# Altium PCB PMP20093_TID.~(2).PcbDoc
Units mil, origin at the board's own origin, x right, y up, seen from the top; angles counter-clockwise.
Board outline 4950 x 3450 mil, 2 copper layers (Top Layer, Bottom Layer), stack 62 mil thick; 35 components, 27 nets, 63 pads, 0 vias.
Unrouted connection lines stored in the file: 39.
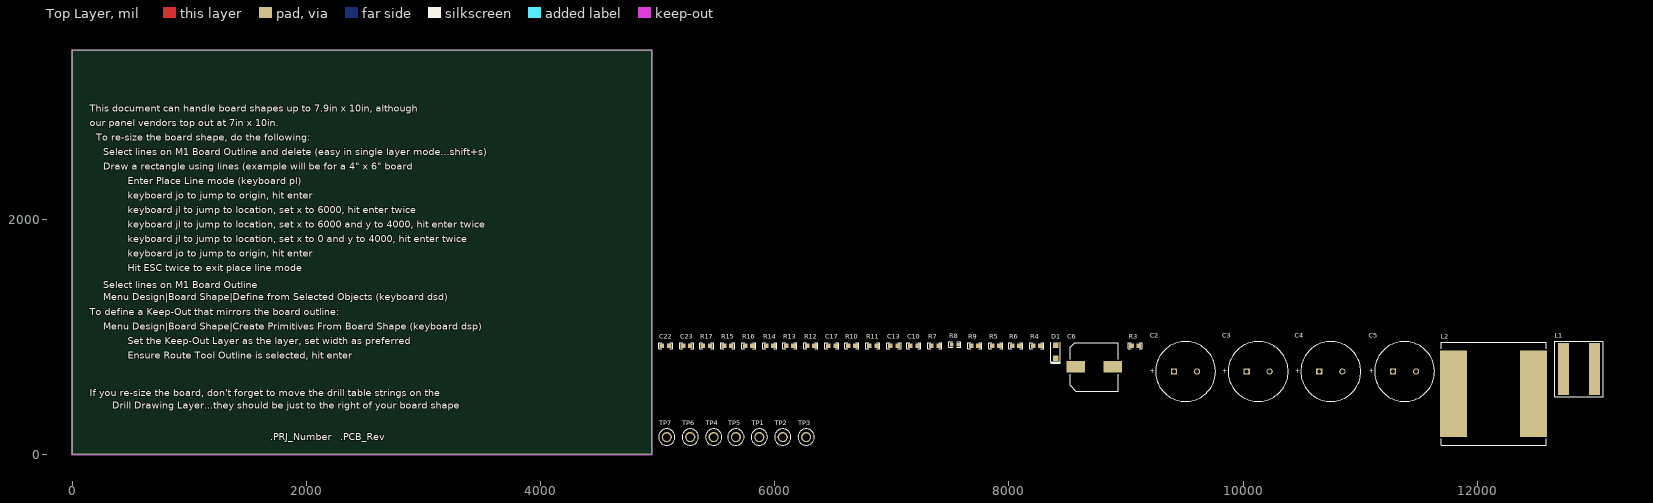
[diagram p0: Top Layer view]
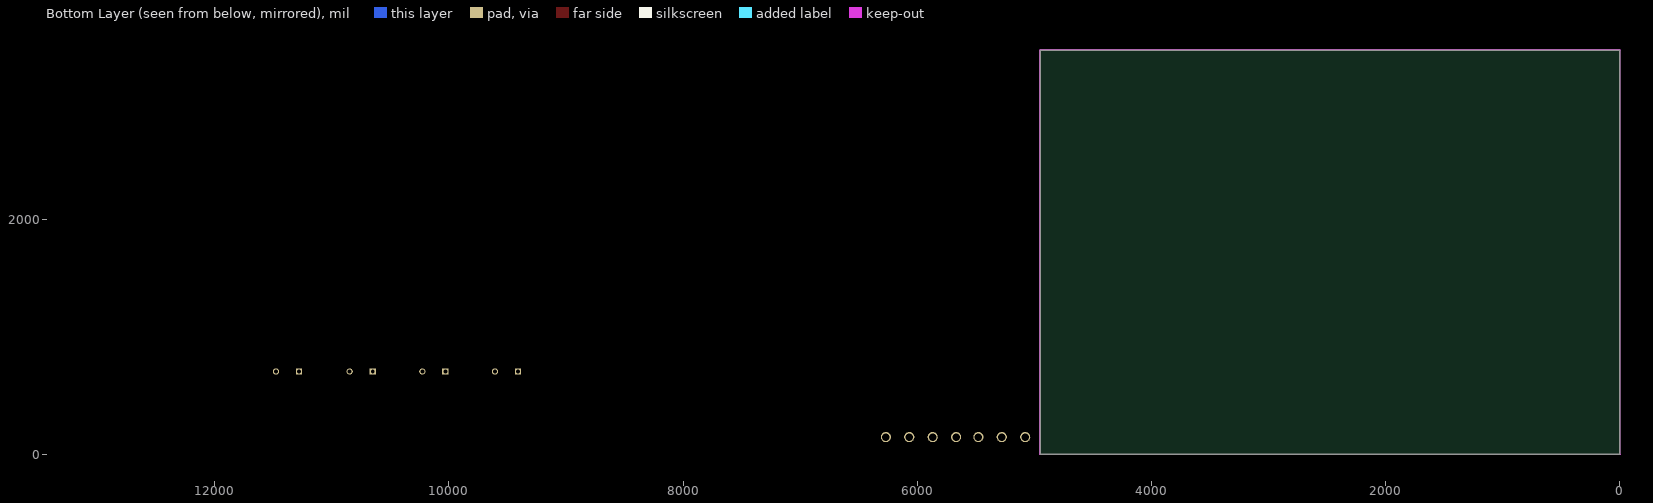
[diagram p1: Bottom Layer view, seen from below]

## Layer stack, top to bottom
Top Solder: solder mask 0.4, Solder Resist, Dk 3.5
Top Layer: signal copper 1.4
Dielectric1: core 59.2, FR-4, Dk 4.8
Bottom Layer: signal copper 1.4
Bottom Solder: solder mask 0.4, Solder Resist, Dk 3.5

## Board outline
0,0 4950,0 4950,3450 0,3450

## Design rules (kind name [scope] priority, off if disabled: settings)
AcuteAngle [All] p1: minimum=4.50000000000000E+0001 checktracksonly=FALSE
AssemblyTestPointUsage [All] p1: valid=2
Clearance Clearance_Keepouts [((IsTrack Or IsArc) And Not InPoly) And IsFree and IsKeepOut vs ((IsTrack Or IsArc) And Not InPoly) And IsFree and IsKeepOut] p1: gap=0
Clearance Clearance_BoardEdge_MountingHoles [OnCopper and InComponentClass('Mounting Holes') vs IsKeepOut] p2: gap=40
Clearance Clearance_BoardEdge_Poly [OnCopper and InPoly vs IsKeepOut] p3: gap=25
Clearance Clearance_BoardEdge [OnCopper and Not InComponentClass('Logo') and not InComponentClass('FiducialMark') and not InRegion(1000,500,4000,800) and Not IsKeepout vs IsKeepOut] p4: gap=75
Clearance Clearance_Poly [InPolygon] p5: gap=25
Clearance [All] p6: gap=7.87
ComponentClearance ComponentClearance_MountingHoles_FiducialMarks [InComponentClass('Mounting Holes') vs InComponentClass('FiducialMark')] p1: gap=50 collisioncheckmode=3 verticalgap=10 showdistances=FALSE
ComponentClearance ComponentClearance_Shunt [InComponentClass('Header') vs InComponentClass('Shunt')] p2: gap=0 collisioncheckmode=3 verticalgap=0 showdistances=FALSE
ComponentClearance ComponentClearance_Logo [InComponentClass('Logo')] p3: gap=50 collisioncheckmode=3 verticalgap=10 showdistances=FALSE
ComponentClearance ComponentClearance_ScrewToNut [(HasFootprint('NY PMS 440 0025 PH')) vs (HasFootprint('Keystone_1902C'))] p4: gap=5 collisioncheckmode=3 verticalgap=10 showdistances=FALSE
ComponentClearance ComponentClearance_MountingHoles [InComponentClass('Mounting Holes')] p5: gap=250 collisioncheckmode=3 verticalgap=100000 showdistances=FALSE
ComponentClearance ComponentClearance_SmallPassives [HasFootprint('0201*') or HasFootprint('0402*') or HasFootprint('0508') or HasFootprint('0603*') or HasFootprint('0612') or HasFootprint('0805*') or HasFootprint('0815*') or HasFootprint('0830*') or HasFootprint('1206*') or HasFootprint('1210*') or HasFootprint('1808*') or HasFootprint('1812*') or HasFootprint('1825*') or HasFootprint('2010*') or HasFootprint('2220*') or HasFootprint('2225*') or HasFootprint('2512*') or HasFootprint('2728*') or HasFootprint('3518*') vs HasFootprint('0201*') or HasFootprint('0402*') or HasFootprint('0508') or HasFootprint('0603*') or HasFootprint('0612') or HasFootprint('0805*') or HasFootprint('0815*') or HasFootprint('0830*') or HasFootprint('1206*') or HasFootprint('1210*') or HasFootprint('1808*') or HasFootprint('1812*') or HasFootprint('1825*') or HasFootprint('2010*') or HasFootprint('2220*') or HasFootprint('2225*') or HasFootprint('2512*') or HasFootprint('2728*') or HasFootprint('3518*')] p6: gap=20 collisioncheckmode=3 verticalgap=10 showdistances=FALSE
ComponentClearance ComponentClearance_THtoSMT [IsThruComponent vs IsSMTComponent] p7: gap=100 collisioncheckmode=3 verticalgap=30 showdistances=FALSE
ComponentClearance ComponentClearance_THtoTH [IsThruComponent vs IsThruComponent] p8: gap=118.11 collisioncheckmode=3 verticalgap=30 showdistances=FALSE
ComponentClearance [All] p9: gap=40 collisioncheckmode=3 verticalgap=10 showdistances=FALSE
DiffPairsRouting [All] p1: maxlimit=100 minlimit=10 mostfreqgap=10 toplayer_minwidth=15 toplayer_maxwidth=15 toplayer_prefwidth=15 bottomlayer_minwidth=15 bottomlayer_maxwidth=15 bottomlayer_prefwidth=15 maxuncoupledlength=1000
FabricationTestPointUsage TestPointUsage [All] p1: valid=2 allowmultiple=FALSE
FabricationTestpoint Testpoint [All] p1: side=3 testpointundercomponent=TRUE minsize=40 maxsize=100 preferedsize=60 minholesize=0 maxholesize=40 preferedholesize=32 testpointgrid=1 allowsidetop=TRUE allowsidebottom=TRUE usegrid=TRUE gridtolerance=0.01
FanoutControl Fanout_LCC [IsLCC] p1: bgadir=Out bgaviamode=Centered fanoutstyle=Auto fanoutdirection=Alternating viagrid=1 // Fanout_LCC (Default Rule)
FanoutControl Fanout_BGA [IsBGA] p2: bgadir=Out bgaviamode=Centered fanoutstyle=Auto fanoutdirection=Alternating viagrid=1 // Fanout_BGA (Default Rule)
FanoutControl Fanout_Default [All] p4: bgadir=Out bgaviamode=Centered fanoutstyle=Auto fanoutdirection=Alternating viagrid=1 // Fanout_Default (Default Rule)
FanoutControl Fanout_Small [(CompPinCount < 5)] p5: bgadir=Out bgaviamode=Centered fanoutstyle=Auto fanoutdirection=OutThenIn viagrid=1 // Fanout_Small (Default Rule)
HoleSize [All] p1: absolutevalues=TRUE maxlimit=251 minlimit=8 maxpercent=80.000 minpercent=20.000
MinimumAnnularRing MinimumAnnularRing_ThermalPadVias [IsVia and InAnyComponent] p1: minimumring=5.91
MinimumAnnularRing [All] p2: minimumring=9
MinimumSolderMaskSliver MinimumSolderMaskSliver_Logo [InComponentClass('Logo') vs InComponentClass('Logo')] p1: minsoldermaskwidth=0.7
MinimumSolderMaskSliver [All] p2: minsoldermaskwidth=3.94
PlaneConnect [All] p1: planeconnectstyle=Relief reliefexpansion=10 reliefentries=4 reliefconductorwidth=10 reliefairgap=10
PolygonConnect [All] p1: connectstyle=Relief reliefconductorwidth=10 reliefentries=4 polygonreliefangle="90 Angle" airgapwidth=10
RoutingVias ThermalPadVias [IsVia and InAnyComponent] p1: holewidth=7.87 width=19.68 viastyle="Through Hole" minholewidth=7.87 minwidth=19.68 maxholewidth=12.99 maxwidth=23.62
RoutingVias [All] p2: holewidth=16 width=34 viastyle="Through Hole" minholewidth=7.87 minwidth=26 maxholewidth=40 maxwidth=65
SilkToBoardRegionClearance [Not ((IsComment or IsDesignator) And (Hide <> 'False')) and not InRegion(1000,500,4000,800)] p1:
SilkToSilkClearance SilkToSilkClearance_Pb-FreeLogo [(HasFootprint('Pb-Free_Overlay_Medium') OR HasFootprint('Pb-Free_Overlay_Small')) vs (HasFootprint('Pb-Free_Overlay_Medium') OR HasFootprint('Pb-Free_Overlay_Small'))] p1: silktosilkclearance=0
SilkToSilkClearance [All] p2: silktosilkclearance=4
SilkToSolderMaskClearance SilkToComonentPadClearance [IsPad and InAnycomponent] p1: minsilkscreentomaskgap=5 clearancetoexposedcopper=TRUE
SilkToSolderMaskClearance "Silk to Solder Mask Opening" [All] p2: minsilkscreentomaskgap=4 clearancetoexposedcopper=FALSE
SolderMaskExpansion [All] p1: expansion=1.97
Width [All] p1: maxlimit=100 minlimit=6 preferedwidth=10 checkconnectedcopper=TRUE
15 further rules are at their usual default settings.

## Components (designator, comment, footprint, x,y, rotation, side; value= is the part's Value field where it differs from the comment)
C2 "50ZL680MEFC12.5X25" ZL_1250x2500 9508,706 r0 top
C3 "50ZL680MEFC12.5X25" ZL_1250x2500 10128,706 r0 top
C4 "50ZL680MEFC12.5X25" ZL_1250x2500 10748,706 r0 top
C5 "50ZL680MEFC12.5X25" ZL_1250x2500 11378,706 r0 top
C6 "EEHZA1V271P" SM_RADIAL_10BMM 8728,746 r0 top
C10 "GRM188R71E474KA12D" 0603 7188,926 r0 top
C13 "C1608X7R1H104K080AA" 0603 7018,926 r0 top
C17 "GRM188R71H102KA01D" 0603 6488,926 r0 top
C22 "C1608X7R1E105K080AB" 0603 5068,926 r0 top
C23 "GRM188R71E474KA12D" 0603 5248,926 r0 top
D1 "PMEG6010CEH" SOD-123F 8398,876 r90 top
L1 "" XAL1010 12868,726 r0 top
L2 "IHLP8787MZER6R8M5A" IHLP8787MZ 12138,516 r0 top
R3 "CRCW0603100RFKEA" 0603 9078,926 r0 top
R4 "CRCW06030000Z0EA" 0603 8238,926 r0 top
R5 "CRCW06030000Z0EA" 0603 7888,926 r0 top
R6 "CRCW06030000Z0EA" 0603 8058,926 r0 top
R7 "CRCW060349K9FKEA" 0603 7368,926 r0 top
R8 "CRCW06033R30JNEA" 0603_HV 7538,936 r0 top
R9 "CRCW0603100RFKEA" 0603 7708,926 r0 top
R10 "CRCW06037K87FKEA" 0603 6658,926 r0 top
R11 "CRCW06030000Z0EA" 0603 6838,926 r0 top
R12 "CRCW0603158KFKEA" 0603 6308,926 r0 top
R13 "CRCW060349K9FKEA" 0603 6128,926 r0 top
R14 "CRCW0603100RFKEA" 0603 5958,926 r0 top
R15 "CRCW060335K7FKEA" 0603 5598,926 r0 top
R16 "CRCW060335K7FKEA" 0603 5778,926 r0 top
R17 "CRCW06031K78FKEA" 0603 5418,926 r0 top
TP1 "5010" Keystone5010 5868,146 r0 top
TP2 "5010" Keystone5010 6068,146 r0 top
TP3 "5010" Keystone5010 6268,146 r0 top
TP4 "5011" Keystone5011 5478,146 r0 top
TP5 "5011" Keystone5011 5668,146 r0 top
TP6 "5010" Keystone5010 5278,146 r0 top
TP7 "5011" Keystone5011 5078,146 r0 top

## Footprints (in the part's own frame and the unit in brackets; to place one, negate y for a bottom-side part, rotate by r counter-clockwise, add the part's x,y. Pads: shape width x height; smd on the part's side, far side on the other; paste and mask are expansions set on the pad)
0603 [mm] "0603 from SM-752 data"
  rect 1x0.95 smd: 1(-0.8,0) 2(0.8,0)
  silkscreen extent -1.52,-0.69 1.52,0.69, body extent -0.87,-0.47 0.87,0.47, height 1
0603_HV [mil] "Ernesto recommended land pattern.  26 mil between pads."
  rect 30x30 smd: 1(-28,0) 2(28,0)
  silkscreen extent -52,-24 52,24, body extent -34,-19 34,19, height 39
IHLP8787MZ [mm] "SMD, 2-Leads, Body 22x22.48mm"
  rect 5.84x18.8 smd: 1(-8.7,0) 2(8.7,0)
  silkscreen extent -11.39,-11.15 11.39,11.15, body extent -11.39,-11.15 11.39,11.15, height 13
Keystone5010 [mil] "Keystone Multipurpose loops"
  round 87 hole 63: 1(0,0)
  silkscreen extent -70,-70 70,70, body extent -63,-63 63,62, height 319
Keystone5011 [mil] "Keystone Multipurpose loops"
  round 87 hole 63: 1(0,0)
  silkscreen extent -70,-70 70,70, body extent -63,-63 63,62, height 319
SM_RADIAL_10BMM [mm] "Nichicon 10x10"
  rect 4x2.5 smd: 1(-4,0) 2(4,0)
  silkscreen extent -5.25,-5.25 5.25,5.25, body extent -5.25,-5.25 5.25,5.25, height 10.5
SOD-123F [mm] "NXP recommended land pattern"
  rect 1.2x1.2 smd paste-0.05: 1(-1.4,0) 2(1.4,0)
  silkscreen extent -2.64,-1.12 2.01,1.12, body extent -1.8,-0.85 1.8,0.85, height 1.2
XAL1010 [mm] "COILCRAFT"
  rect 2.38x11.31 smd: 1(-3.325,0) 2(3.325,0)
  silkscreen extent -5.3,-6 5.3,6, body extent -5.25,-5.9 5.25,5.9, height 10
ZL_1250x2500 [mm] "TH, 2-Leads, Dia 12.5mm, Lead Spacing 5mm"
  rect 1.35x1.35 hole 0.85: 1(-2.5,0)
  round 1.35 hole 0.85: 2(2.5,0)
  silkscreen extent -6.5,-6.5 6.5,6.5, body extent -6.45,-6.49 6.49,6.49, height 27.01

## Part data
C2 C3 C4 C5: library part 50ZL560MEFC12.5X25, "CAP, AL, 680 µF, 50 V, +/- 20%, 2.86A, 0.021 ohm, TH"
C6: "CAP, Polymer Hybrid, 270 µF, 35 V, +/- 20%, 20 ohm, 10x10 SMD"
C10 C23: "CAP, CERM, 0.47uF, 25V, +/-10%, X7R, 0603"
C13: "CAP, CERM, 0.1 µF, 50 V, +/- 10%, X7R, 0603"
C17: "CAP, CERM, 1000pF, 50V, +/-10%, X7R, 0603"
C22: "CAP, CERM, 1 µF, 25 V, +/- 10%, X7R, 0603"
D1: library part PMEG6010CEH,115, "Diode, Schottky, 60V, 1A, SOD-123F"
L1: library part XAL1010-222MEB, "Inductor, SMD, alternate footprint"
L2: library part IHLP8787MZER100M5A, "Inductor, Shielded, 6.8 µH, 36A, 0.00284 ohm, AEC-Q200 Grade 0, SMD"
R3 R9: "RES, 100, 1%, 0.1 W, 0603"
R4 R5 R6 R11: "RES, 0, 5%, 0.1 W, 0603"
R7 R13: "RES, 49.9k ohm, 1%, 0.1W, 0603"
R8: "RES, 3.3 ohm, 5%, 0.1W, 0603"
R10: "RES, 7.87 k, 1%, 0.1 W, 0603"
R12: "RES, 158 k, 1%, 0.1 W, 0603"
R14: "RES, 100 ohm, 1%, 0.1W, 0603"
R15 R16: "RES, 35.7 k, 1%, 0.1 W, 0603"
R17: "RES, 1.78 k, 1%, 0.1 W, 0603"
TP1 TP2 TP3 TP6: "Test Point, Multipurpose, Red, TH"
TP4 TP5 TP7: "Test Point, Multipurpose, Black, TH"

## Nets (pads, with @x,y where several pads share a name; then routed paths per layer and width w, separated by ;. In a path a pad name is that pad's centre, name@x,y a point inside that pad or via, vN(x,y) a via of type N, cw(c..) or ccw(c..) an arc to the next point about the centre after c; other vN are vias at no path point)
GND: C2.2 C3.2 C4.2 C5.2 C6.2 C13.1 C17.2 C22.2 C23.1 R10.1 R15.1 R16.1 R17.1 TP4.1 TP5.1 TP7.1
NetC1_1: C2.1 C3.1 C4.1 C5.1 C13.2 R14.2 TP3.1
NetC1_2: 
NetC6_1: C6.1 R7.2 R8.1 R9.2 TP1.1
NetC10_1: C10.1 D1.1
NetC10_2: C10.2 L1.2 L2.2 TP2.1
NetC11_1: R3.1
NetC11_2: R9.1
NetC17_1: C17.1 R7.1 R10.2
NetC18_1: R8.2
NetC19_1: R12.1 R13.1 R17.2
NetC19_2: 
NetC20_1: R12.2
NetC21_1: D1.2
NetC22_1: C22.1
NetC23_2: C23.2
NetJ3_2: 
NetL1_1: L1.1 L2.1 R3.2
NetQ1_4: R5.2
NetQ2_4: R6.2
NetQ3_4: R4.1
NetQ4_4: R11.2
NetR4_2: R4.2 R11.1
NetR5_1: R5.1 R6.1
NetR13_2: R13.2 R14.1 TP6.1
NetR15_2: R15.2
NetR16_2: R16.2

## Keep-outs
Keep-Out Layer:
  lines w10: -5,0 ccw(c0,0) 0,-5 ; -5,0 ccw(c0,0) 0,-5 ; -5,0 -5,3450 ; -5,3450 cw(c0,3450) 0,3455 ; -5,3450 cw(c0,3450) 0,3455 ; 0,-5 4950,-5 ; 0,3455 4950,3455 ; 4950,-5 ccw(c4950,0) 4955,0 ; 4950,-5 ccw(c4950,0) 4955,0 ; 4950,3455 cw(c4950,3450) 4955,3450 ; 4950,3455 cw(c4950,3450) 4955,3450 ; 4955,0 4955,3450
  text ".Layer_Name" at 577,-858.49 h60

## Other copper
Top Layer:
  text ".Layer_Name" at 577,-858.49 h60
Bottom Layer:
  text ".Layer_Name" at 577,-858.49 h60

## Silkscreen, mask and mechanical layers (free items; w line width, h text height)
Top Overlay:
  text "This document can handle board shapes up to 7.9in x 10in, although" at 150,2925 h60
  text "our panel vendors top out at 7in x 10in." at 150,2800.94 h60
  text "To re-size the board shape, do the following:" at 205,2676.88 h60
  text "Select lines on M1 Board Outline and delete (easy in single layer mode...shift+s)" at 265,2552.82 h60
  text "Draw a rectangle using lines (example will be for a 4\" x 6\" board" at 265,2428.76 h60
  text "Enter Place Line mode (keyboard pl)" at 475,2304.71 h60
  text "keyboard jo to jump to origin, hit enter" at 475,2180.65 h60
  text "keyboard jl to jump to location, set x to 6000, hit enter twice" at 475,2056.59 h60
  text "keyboard jl to jump to location, set x to 6000 and y to 4000, hit enter twice" at 475,1932.53 h60
  text "keyboard jl to jump to location, set x to 0 and y to 4000, hit enter twice" at 475,1808.47 h60
  text "keyboard jo to jump to origin, hit enter" at 475,1684.41 h60
  text "Hit ESC twice to exit place line mode" at 475,1560.35 h60
  text "Select lines on M1 Board Outline" at 265,1416.3 h60
  text "Menu Design|Board Shape|Define from Selected Objects (keyboard dsd)" at 265,1312.24 h60
  text "To define a Keep-Out that mirrors the board outline:" at 150,1188.18 h60
  text "Menu Design|Board Shape|Create Primitives From Board Shape (keyboard dsp)" at 265,1064.12 h60
  text "Set the Keep-Out Layer as the layer, set width as preferred" at 475,940.06 h60
  text "Ensure Route Tool Outline is selected, hit enter" at 475,816 h60
  text "If you re-size the board, don't forget to move the drill table strings on the" at 150,493 h60
  text "Drill Drawing Layer...they should be just to the right of your board shape" at 343,387 h60
  text ".PRJ_Number" at 1690,120 h60
  text ".PCB_Rev" at 2290,120 h60
  text ".Layer_Name" at 577,-858.49 h60
Bottom Overlay:
  text ".Layer_Name" at 577,-858.49 h60
Top Paste:
  text ".Layer_Name" at 577,-858.49 h60
Bottom Paste:
  text ".Layer_Name" at 577,-858.49 h60
Top Solder:
  text ".Layer_Name" at 577,-858.49 h60
  text ".Layer_Name" at 577,-858.49 h60
Bottom Solder:
  text ".Layer_Name" at 577,-858.49 h60
Drill Guide:
  text ".Layer_Name" at 577,-858.49 h60
M1 Board Outline:
  the board outline again, w10
  text ".Layer_Name" at 577,-858.49 h60
M2 Board Dimensions:
  rectangle: 0,-275 125,-150
  rectangle: 125,-400 500,-275
  lines w7: 0,-275 1000,-275 ; 125,-400 125,-150 ; 250,-400 250,-150 ; 500,-400 500,-150 ; 750,-400 750,-150 ; 0,-400 1000,-400 1000,-150 0,-150 0,-400
  text ".Layer_Name" at 577,-858.49 h60
M3 3D STEP Top:
  text ".Layer_Name" at 577,-858.49 h60
M4 3D STEP Bottom:
  text ".Layer_Name" at 577,-858.49 h60
M5 Assembly Top:
  lines w10: -292,-930.17 6308,-930.17 ; -292,-726.83 6310,-726.83 ; -292,-523.5 -292,-1133.5 3713,-1133.5 6310,-1133.5 6310,-523.5 -291.5,-523.5 -291.5,-1133.5 1284,-1133.5 ; 2173,-1133.5 2173,-523.5 ; 3440,-726.83 3440,-523.5 ; 4280,-726.83 4280,-523.5 ; 4902,-1140 4902,-937.17
  text "COMPONENTS MARKED 'DNP' SHOULD NOT BE POPULATED." at 1153.5,-318.5 h60
  text "ASSEMBLY VARIANT:" at 1153,-434 h60
  text ".VariantName" at 2189,-434 h60
  text "PCB VIEWED FROM TOP SIDE" at -228.5,-655.67 h60
  text "BOARD #:" at 2248,-655.67 h60
  text ".PRJ_Number" at 2793.5,-655.67 h60
  text "REV:" at 3638,-655.67 h60
  text ".PCB_Rev" at 3929.5,-655.67 h60
  text "SVN REV:" at 4476,-655.67 h60
  text ".VersionControl_RevNumber" at 4982,-655.67 h60
  text "TID #:" at 2248,-859 h60
  text ".TID" at 2793.5,-859 h60
  text "PLOT NAME =" at -228.5,-1064.34 h60
  text ".plot_File_Name" at 577,-1064.34 h60
  text "GENERATED    :" at 2250,-1064.34 h60
  text ".Print_Date" at 3119.5,-1064.34 h60
  text ".Print_Time" at 3848.5,-1064.34 h60
  text "TEXAS INSTRUMENTS" at 5113,-1064.34 h60
M6 Assembly Bottom:
  lines w10: -292.5,-727.33 6309.5,-727.33 ; -290.5,-930.67 6309.5,-930.67 ; 1115.5,-1140.5 1115.5,-937.67 ; 1737.5,-727.33 1737.5,-524 ; 2577.5,-727.33 2577.5,-524 ; 3844.5,-1134 3844.5,-524 ; 4733.5,-1134 6309,-1134 6309,-524 -292.5,-524 -292.5,-1134 2304.5,-1134 6309.5,-1134 6309.5,-524
  text "COMPONENTS MARKED 'DNP' SHOULD NOT BE POPULATED." at 6102,-318 h60
  text ".VariantName" at 5058,-434 h60
  text "ASSEMBLY VARIANT:" at 6097,-434 h60
  text ".VersionControl_RevNumber" at 1035.5,-656.17 h60
  text "SVN REV:" at 1541.5,-656.17 h60
  text ".PCB_Rev" at 2088,-656.17 h60
  text "REV:" at 2379.5,-656.17 h60
  text ".PRJ_Number" at 3224,-656.17 h60
  text "BOARD #:" at 3769.5,-656.17 h60
  text "PCB VIEWED FROM BOTTOM SIDE" at 6246,-656.17 h60
  text ".TID" at 3224,-859.5 h60
  text "TID #:" at 3769.5,-859.5 h60
  text "TEXAS INSTRUMENTS" at 904.5,-1064.84 h60
  text ".Print_Time" at 2169,-1064.84 h60
  text ".Print_Date" at 2898,-1064.84 h60
  text "GENERATED    :" at 3767.5,-1064.84 h60
  text ".plot_File_Name" at 5440.5,-1064.84 h60
  text "PLOT NAME =" at 6246,-1064.84 h60
M9 Title Sheet:
  drawing of 57 lines, arcs and shapes, not listed
  text "1" at 739.84,8036.5 h70
  text "2" at 3235.5,8036.5 h70
  text "3" at 5724.84,8036.5 h70
  text "4" at 8231.51,8036.5 h70
  text "5" at 10730.5,8036.5 h70
  text "6" at 13235.5,8036.5 h70
  text "A" at -416.5,6893.5 h70
  text "A" at 14383.5,6893.5 h70
  text "B" at -416.5,4513.5 h70
  text "B" at 14383.5,4513.5 h70
  text "C" at -416.5,2138.5 h70
  text "C" at 14383.5,2138.5 h70
  text "PROJECT TITLE:" at 11343.5,277.5 h45
  text ".PRJ_Title" at 11393.5,144.17 h70
  text "DESIGNED FOR:" at 11343.5,-23.5 h45
  text ".PRJ_Customer" at 11393.5,-163.5 h70
  text "D" at -416.5,-231.5 h70
  text "D" at 14383.5,-231.5 h70
  text "FILE NAME:" at 11343.5,-323.5 h45
  text ".PCB_File_Name_No_Path" at 11393.5,-443.5 h70
  text "Texas Instruments (TI) and/or its licensors do not warrant the accuracy or completeness of this specification" at 6374,-605.34 h45
  text "ENGINEER:" at 11343.5,-613.5 h45
  text "LAYOUT BY:" at 12848.5,-613.5 h45
  text "or any information contained therein. TI and/or its licensors do not warrant that this design will meet" at 6329.01,-718 h45
  text ".PRJ_Engineer" at 11393.5,-768.49 h70
  text ".PCB_Layout" at 12899,-768.49 h70
  text "the specifications, will be suitable for your application or fit for any particular purpose, or will operate in" at 6329.01,-830.67 h45
  text ".Layer_Name" at 577,-858.49 h60
  text "ALTIUM DESIGNER VERSION:" at 12848.5,-923.5 h45
  text "an implementation. TI and/or its licensors do not warrant that the design is production worthy. You should" at 6329.01,-943.33 h45
  text "completely validate and test your design implementation to confirm the system functionality for your application." at 6374,-1056 h45
  text ".print_Scale" at 11393.5,-1056.83 h70
  text ".Application_BuildNumber" at 12899,-1056.83 h70
  text "1" at 739.84,-1263.5 h70
  text "2" at 3235.5,-1263.5 h70
  text "3" at 5724.84,-1263.5 h70
  text "4" at 8231.51,-1263.5 h70
  text "5" at 10730.5,-1263.5 h70
  text "6" at 13235.5,-1263.5 h70
M10 Fab Notes:
  drawing of 173 lines, arcs and shapes, not listed
  text "DESIGN INFORMATION" at 12377.02,6201 h60
  text "MIN. TRACK WIDTH:" at 11732.46,6021 h60
  text "8" at 12828.7,6021 h60
  text "MIL" at 12983.46,6021 h60
  text "MIN. CLEARANCE:" at 11732.46,5889 h60
  text "0.2" at 12768.7,5889 h60
  text "mm" at 12983.46,5889 h60
  text "MIN. VIA PAD SIZE:" at 11732.46,5757 h60
  text "24" at 12798.71,5757 h60
  text "MIL" at 12983.46,5757 h60
  text "0.05mm (2MIL)" at 12427.46,5615.29 h60
  text "MINIMUM ANNULAR RING" at 11403.23,5611 h60
  text "EXTERNAL" at 13135.46,5611 h60
  text "PER" at 11603.23,5493 h60
  text "IPC-D-275 CLASS 2 LEVEL C" at 11823.23,5493 h60
  text "MIL, HOLES" at 13311.46,5380.71 h60
  text "+/-" at 12919,5380 h60
  text "+/-" at 13773,5380 h60
  text "REGISTRATION TOLERANCES:" at 11403.23,5375 h60
  text "METAL" at 12603,5375 h60
  text "5" at 13179.2,5375 h60
  text "3" at 14012.2,5375 h60
  text "MIL" at 14128.46,5375 h60
  text "+/-" at 13773,5262 h60
  text "HOLE SIZE TOLERANCE (UNLESS OTHERWISE SPECIFIED):" at 11403.23,5257 h60
  text "3" at 14012.2,5257 h60
  text "MIL" at 14128.46,5257 h60
  text "MATERIAL:" at 11328.46,5047.54 h60
  text "FR-4 High Tg" at 12314.9,4907.21 h60
  text "FR-408" at 11749.46,4898.64 h60
  text "OTHER" at 13237.46,4898.64 h60
  text "X" at 12160,4895 h60
  text "62 MIL (1.6mm) +/-10%" at 12069.56,4735.92 h60
  text "THICKNESS:" at 11403.23,4731.64 h60
  text "X" at 11941.4,4731.64 h60
  text "OTHER" at 13354.46,4731.64 h60
  text "TOLERANCE:" at 11403.23,4573.64 h60
  text "X" at 12242.53,4573.64 h60
  text "ANSI IPC-6012 TYPE 3 CLASS 2" at 12429.48,4573.64 h60
  text "OTHER +/-" at 12429.46,4417.64 h60
  text "BOW & TWIST:" at 11403.23,4260.64 h60
  text "X" at 12242.53,4260.64 h60
  text "ANSI IPC-6012 TYPE 3 CLASS 2" at 12429.48,4260.64 h60
  text "OTHER +/-" at 12429.46,4102.13 h60
  text "DRILLING:" at 11328.46,3963.64 h60
  text "REFERENCE:" at 11403.23,3846.64 h60
  text "X" at 12051.46,3846.64 h60
  text "AS SHOWN" at 12238.46,3846.64 h60
  text "X" at 12952.46,3846.64 h60
  text "NC_DRILL FILES" at 13089.46,3846.64 h60
  text "PTH COPPER THICKNESS:" at 11403.23,3688.64 h60
  text "X" at 12533.46,3688.64 h60
  text "20-30 um" at 12670.46,3688.64 h60
  text "OTHER" at 13387.46,3688.64 h60
  text "BOARD FINISH:" at 11328.46,3529.64 h60
  text "SILKSCREEN:" at 11483.68,3411.64 h60
  text "X" at 12432.46,3411.64 h60
  text "TOP" at 12558.46,3411.64 h60
  text "X" at 12942.46,3411.64 h60
  text "BOTTOM" at 13069.46,3411.64 h60
  text "SILKSCREEN COLOR:" at 11483.68,3244.64 h60
  text "X" at 12431.42,3244.64 h60
  text "WHITE" at 12558.46,3244.64 h60
  text "OTHER" at 13069.46,3244.64 h60
  text "X" at 12562.42,3085.44 h60
  text "GREEN" at 12689.46,3085.44 h60
  text "OTHER" at 13307.46,3085.44 h60
  text "SOLDER RESIST COLOR:" at 11483.68,3074.64 h60
  text "X" at 12562.42,2915.44 h60
  text "MATTE" at 12689.46,2915.44 h60
  text "SEMI-GLOSS" at 13307,2914.8 h60
  text "IMMERSION GOLD (ENIG)" at 12389.46,2726.92 h60
  text "ENEPIG" at 13727,2723.64 h60
  text "SURFACE FINISH:" at 11328.46,2722.64 h60
  text "X" at 12202.51,2722.64 h60
  text "IMM. TIN/SILVER OR EQUIV" at 11658,2565.64 h60
  text "OTHER" at 13089.46,2565.64 h60
  text "ARRAY/PANEL:" at 11328.46,2386.64 h60
  text "CUT AND TRIM PER M1 BOARD OUTLINE" at 12389.46,2382.35 h60
  text "N.C. ROUTE" at 12389.46,2230.64 h60
  text "X" at 13068.46,2230.64 h60
  text "V. SCORE" at 13255.46,2230.64 h60
  text "CERTIFICATION:" at 11328.46,2093.64 h60
  text "MATERIALS AND WORKMANSHIP FOR ALL PCBS" at 12053.46,2093.64 h60
  text "TO MEET OR EXCEED THE REQUIREMENTS OF:" at 12053.46,1995.64 h60
  text "X" at 11679.96,1859.13 h60
  text "ANSI IPC-A-600F CLASS ->" at 11818.96,1859.13 h60
  text "X" at 13458.02,1859.13 h60
  text "2" at 13576.96,1859.14 h60
  text "1" at 13261.96,1857.64 h60
  text "3" at 13930.96,1857.64 h60
  text "X" at 12494.02,1699.64 h60
  text "RoHS" at 12630.96,1699.64 h60
  text "OTHER" at 13275.36,1699.64 h60
  text "PER ORDER" at 13672.42,1699.64 h60
  text "ALL BOARDS MUST MEET OR EXCEED UL94-V0 REQUIREMENTS." at 11356,1534 h60
  text "PCB MUST BEAR THE UL94V-0 UL REGISTERED MATERIAL ID NUMBER" at 11356,1414 h60
  text "ADDITIONAL REQUIREMENTS:" at 11328.46,1240.64 h60
  text "MICROSECTION:" at 11403.23,1125.64 h60
  text "YES" at 12308.96,1125.64 h60
  text "REQUIRED" at 13170.46,969.49 h60
  text "BARE BOARD ELEC. TEST:" at 11403.23,966.64 h60
  text "NONE" at 12708.96,966.64 h60
  text "X" at 13043.46,966.64 h60
  text "PER ORDER" at 13762.46,966.64 h60
  text ".Layer_Name" at 577,-858.49 h60
M11 Gerber Information:
  lines w10: -292,-930.17 6308,-930.17 ; -292,-726.83 6310,-726.83 ; -292,-523.5 -292,-1133.5 3713,-1133.5 6310,-1133.5 6310,-523.5 -291.5,-523.5 -291.5,-1133.5 1284,-1133.5 ; 2173,-1133.5 2173,-523.5 ; 3440,-726.83 3440,-523.5 ; 4280,-726.83 4280,-523.5 ; 4902,-1140 4902,-937.17
  text "ALL ARTWORK VIEWED FROM TOP SIDE" at -228.5,-655.67 h60
  text "BOARD #:" at 2248,-655.67 h60
  text ".PRJ_Number" at 2793.5,-655.67 h60
  text "REV:" at 3638,-655.67 h60
  text ".PCB_Rev" at 3929.5,-655.67 h60
  text "SVN REV:" at 4476,-655.67 h60
  text ".VersionControl_RevNumber" at 4982,-655.67 h60
  text "LAYER NAME =" at -228.5,-858.49 h60
  text "TID #:" at 2248,-859 h60
  text ".TID" at 2793.5,-859 h60
  text "PLOT NAME =" at -228.5,-1064.34 h60
  text ".plot_File_Name" at 577,-1064.34 h60
  text "GENERATED    :" at 2250,-1064.34 h60
  text ".Print_Date" at 3119.5,-1064.34 h60
  text ".Print_Time" at 3848.5,-1064.34 h60
  text "TEXAS INSTRUMENTS" at 5113,-1064.34 h60
M12 Stackup:
  drawing of 191 lines, arcs and shapes, not listed
  text "Layer" at 9790.58,7830 h60
  text "Name" at 10200.49,7830 h60
  text "Material" at 11130.23,7830 h60
  text "Thickness" at 11990,7830 h60
  text "Constant" at 12639.84,7830 h60
  text "Board Layer Stack" at 13209.7,7830 h60
  text "1" at 9790.58,7710 h60
  text "Top Overlay" at 10200.49,7710 h60
  text "2" at 9790.58,7590 h60
  text "Top Solder" at 10200.49,7590 h60
  text "Solder Resist" at 11130.23,7590 h60
  text "0.40mil" at 11990,7590 h60
  text "3.5" at 12639.84,7590 h60
  text "3" at 9790.58,7470 h60
  text "Top Layer" at 10200.49,7470 h60
  text "Copper" at 11130.23,7470 h60
  text "1.40mil" at 11990,7470 h60
  text "4" at 9790.58,7350 h60
  text "Dielectric1" at 10200.49,7350 h60
  text "FR-4" at 11130.23,7350 h60
  text "59.20mil" at 11990,7350 h60
  text "4.8" at 12639.84,7350 h60
  text "5" at 9790.58,7230 h60
  text "Bottom Layer" at 10200.49,7230 h60
  text "Copper" at 11130.23,7230 h60
  text "1.40mil" at 11990,7230 h60
  text "6" at 9790.58,7110 h60
  text "Bottom Solder" at 10200.49,7110 h60
  text "Solder Resist" at 11130.23,7110 h60
  text "0.40mil" at 11990,7110 h60
  text "3.5" at 12639.84,7110 h60
  text "7" at 9790.58,6990 h60
  text "Bottom Overlay" at 10200.49,6990 h60
  text ".Layer_Name" at 577,-858.49 h60
M13 Component Bodies Top:
  text ".Layer_Name" at 577,-858.49 h60
M14 Component Bodies Bottom:
  text ".Layer_Name" at 577,-858.49 h60
M15 Courtyards Top:
  text ".Layer_Name" at 577,-858.49 h60
M16 Courtyards Bottom:
  text ".Layer_Name" at 577,-858.49 h60
Drill Drawing:
  lines w10: 5536.09,3128.15 5549.9,3128.15 5563.72,3114.34 5577.53,3128.15 5591.34,3128.15 5577.53,3141.96 5591.34,3155.78 5577.53,3155.78 5563.72,3169.59 5549.9,3155.78 5536.09,3155.78 5549.9,3141.96 5536.09,3128.15 ; 5536.09,3293.91 5591.34,3293.91 5563.72,3238.66 5536.09,3293.91
  lines w12: 5486,3077.04 7464.02,3077.04 ; 5486,3325.68 7464.02,3325.68 ; 5823.86,2952.72 5823.86,3450 ; 6155.86,2952.72 6155.86,3450 ; 6792.43,2952.72 6792.43,3450 ; 7051.57,2952.72 7051.57,3450 ; 5486,2952.72 7464.02,2952.72 7464.02,3450 5486,3450 5486,2952.72
  text "Symbol" at 5560.59,3362.98 h72
  text "Quantity" at 5861.16,3362.98 h72
  text "Finished Hole Size" at 6193.16,3362.98 h72
  text "Plated" at 6829.72,3362.98 h72
  text "Hole Type" at 7088.86,3362.98 h72
  text "8" at 5861.16,3238.66 h60
  text "33.46mil (0.850mm)" at 6193.16,3238.66 h60
  text "PTH" at 6829.72,3238.66 h60
  text "Round" at 7088.86,3238.66 h60
  text "7" at 5861.16,3114.34 h60
  text "63.00mil (1.600mm)" at 6193.16,3114.34 h60
  text "PTH" at 6829.72,3114.34 h60
  text "Round" at 7088.86,3114.34 h60
  text "15 Total" at 5861.16,2990.02 h60
  text ".Layer_Name" at 577,-858.49 h60

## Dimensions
0,-400 to 1000,-400 on M2 Board Dimensions
0,0 to 0,3450 on M2 Board Dimensions
0,0 to 4950,0 on M2 Board Dimensions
